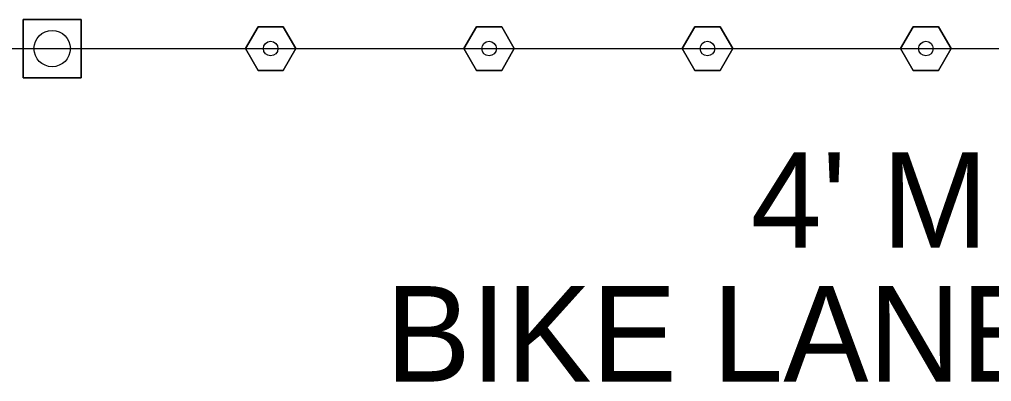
# Model space of a CAD drawing. Extents: x 99999.1 to 100095.7, y 99995 to 100010.7.
# Drawn here: x 100048.279 to 100048.991, y 100008.9 to 100009.166 of the extents above; entities that cross this region are included whole.
import ezdxf

# ---------------------------------------------------------------- set-up
doc = ezdxf.new("R2010")
doc.units = 0
for name, color, linetype in [('RD_MK_LineEdgeWhite', 7, 'Continuous'), ('TR_WZ_TrafficCone', 7, 'Continuous'), ('TR_WZ_TubularMarker', 7, 'Continuous'), ('TR_WZ_WorkZoneTextCurrent', 7, 'Continuous')]:
    doc.layers.add(name, color=color, linetype=linetype)

msp = doc.modelspace()

# ---------------------------------------------------------------- linework, layer by layer
at = {"layer": 'RD_MK_LineEdgeWhite'}
msp.add_line((100045.38423, 100009.14433), (100049.30157, 100009.14433), dxfattribs=at)
at = {"layer": 'TR_WZ_TrafficCone'}
for points in [[(100048.28153, 100009.16566), (100048.3242, 100009.16566), (100048.3242, 100009.123), (100048.28153, 100009.123), (100048.28153, 100009.16566)], [(100048.28153, 100009.123), (100048.3242, 100009.123), (100048.3242, 100009.16566), (100048.28153, 100009.16566), (100048.28153, 100009.123)]]:
    msp.add_lwpolyline(points, dxfattribs=at)
msp.add_circle((100048.30287, 100009.14433), 0.01333, dxfattribs=at)
at = {"layer": 'TR_WZ_TubularMarker'}
for points in [[(100048.44446, 100009.14433), (100048.4537, 100009.16033), (100048.47217, 100009.16033), (100048.48141, 100009.14433), (100048.47217, 100009.12833), (100048.4537, 100009.12833)], [(100048.60446, 100009.14433), (100048.6137, 100009.16033), (100048.63217, 100009.16033), (100048.64141, 100009.14433), (100048.63217, 100009.12833), (100048.6137, 100009.12833)], [(100048.76446, 100009.14433), (100048.7737, 100009.16033), (100048.79217, 100009.16033), (100048.80141, 100009.14433), (100048.79217, 100009.12833), (100048.7737, 100009.12833)], [(100048.92446, 100009.14433), (100048.9337, 100009.16033), (100048.95217, 100009.16033), (100048.96141, 100009.14433), (100048.95217, 100009.12833), (100048.9337, 100009.12833)]]:
    msp.add_lwpolyline(points, close=True, dxfattribs=at)
for points in [[(100048.4537, 100009.12833), (100048.47217, 100009.12833), (100048.48141, 100009.14433), (100048.47217, 100009.16033), (100048.4537, 100009.16033), (100048.44446, 100009.14433), (100048.4537, 100009.12833)], [(100048.6137, 100009.12833), (100048.63217, 100009.12833), (100048.64141, 100009.14433), (100048.63217, 100009.16033), (100048.6137, 100009.16033), (100048.60446, 100009.14433), (100048.6137, 100009.12833)], [(100048.7737, 100009.12833), (100048.79217, 100009.12833), (100048.80141, 100009.14433), (100048.79217, 100009.16033), (100048.7737, 100009.16033), (100048.76446, 100009.14433), (100048.7737, 100009.12833)], [(100048.9337, 100009.12833), (100048.95217, 100009.12833), (100048.96141, 100009.14433), (100048.95217, 100009.16033), (100048.9337, 100009.16033), (100048.92446, 100009.14433), (100048.9337, 100009.12833)]]:
    msp.add_lwpolyline(points, dxfattribs=at)
for centre in [(100048.46293, 100009.14433), (100048.62293, 100009.14433), (100048.78293, 100009.14433), (100048.94293, 100009.14433)]:
    msp.add_circle(centre, 0.00533, dxfattribs=at)

# ---------------------------------------------------------------- texts
at = {"layer": 'TR_WZ_WorkZoneTextCurrent'}
for s, p in [("4' MIN", (100048.81469, 100008.99833)), ('BIKE LANE', (100048.54712, 100008.90033))]:
    msp.add_text(s, height=0.07, dxfattribs=at).set_placement(p)

doc.saveas('drawing.dxf')
